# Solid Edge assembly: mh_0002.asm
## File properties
Title: work_unit
Author: edge
Template: normal.asm
Last saved by: edge
Revision: 22
Application: Solid Edge
文書内容のタイプ: 1
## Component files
mh_0008.par
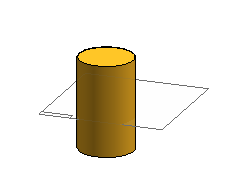
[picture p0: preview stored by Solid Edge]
